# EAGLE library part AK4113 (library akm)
Digital Audio Receiver (DIR) 6:1 Selector, 24-Bit, 192 kHz
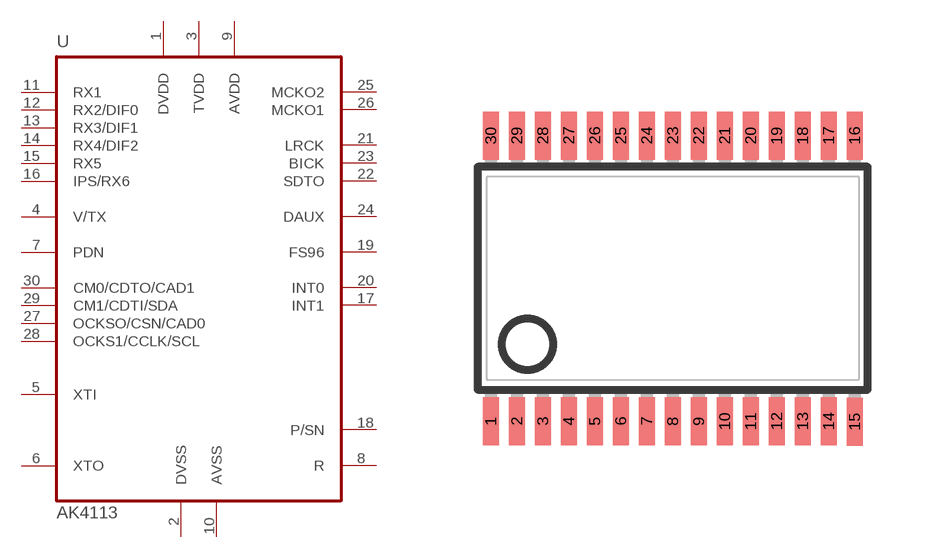
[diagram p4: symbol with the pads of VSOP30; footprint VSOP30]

Designator prefix U

## AK4113  [VSOP30]
1  DVDD  pwr
2  DVSS  pwr
3  TVDD  pwr
4  V/TX  out
5  XTI  in
6  XTO  out
7  PDN  in
8  R  pas
9  AVDD  pwr
10  AVSS  pwr
11  RX1  in
12  RX2/DIF0  in
13  RX3/DIF1  in
14  RX4/DIF2  in
15  RX5  in
16  IPS/RX6  in
17  INT1  out
18  P/SN  in
19  FS96
20  INT0  out
21  LRCK
22  SDTO  out
23  BICK
24  DAUX
25  MCKO2  out
26  MCKO1  out
27  OCKSO/CSN/CAD0
28  OCKS1/CCLK/SCL
29  CM1/CDTI/SDA
30  CM0/CDTO/CAD1

## Footprint VSOP30 (pad centres in mm)
VSOP30 9.7 x 5.6 mm, pitch .65 mm
smd 0.4 x 1.2: 1 -4.55,-3.57; 2 -3.9,-3.57; 3 -3.25,-3.57; 4 -2.6,-3.57; 5 -1.95,-3.57; 6 -1.3,-3.57; 7 -0.65,-3.57; 8 0,-3.57; 9 0.65,-3.57; 10 1.3,-3.57; 11 1.95,-3.57; 12 2.6,-3.57; 13 3.25,-3.57; 14 3.9,-3.57; 15 4.55,-3.58; 16 4.55,3.57; 17 3.9,3.57; 18 3.25,3.57; 19 2.6,3.57; 20 1.95,3.57; 21 1.3,3.57; 22 0.65,3.57; 23 0,3.57; 24 -0.65,3.57; 25 -1.3,3.57; 26 -1.95,3.57; 27 -2.6,3.57; 28 -3.25,3.57; 29 -3.9,3.57; 30 -4.55,3.57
